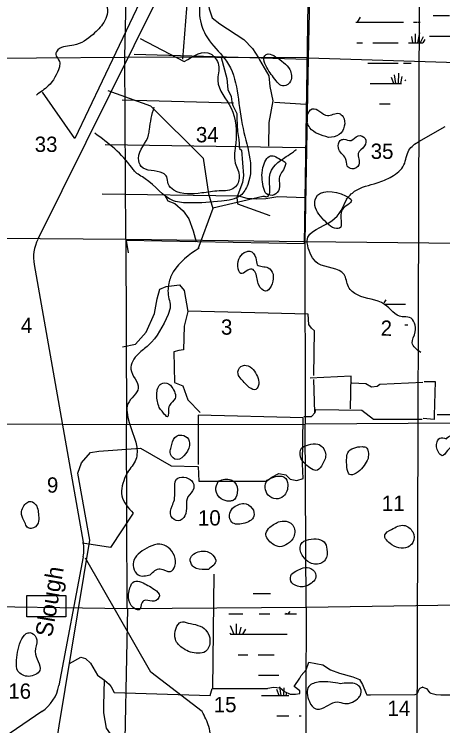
# Model space of a CAD drawing. Extents: x 408847 to 817539, y 923858 to 1151780.
# Drawn here: x 522466 to 535062, y 1031794 to 1052714 of the extents above; entities that cross this region are included whole.
import ezdxf

# ---------------------------------------------------------------- set-up
doc = ezdxf.new("R2010")
doc.units = 0
for name, color, linetype in [('Lakes and Ponds', 7, 'Continuous'), ('Level 42', 7, 'Continuous'), ('Level 43', 7, 'Continuous'), ('Local Roads Paved', 7, 'Continuous'), ('Narrow River Creek and Branch and Slough', 7, 'Continuous'), ('Quad Borders', 7, 'Continuous'), ('Section Lines', 7, 'Continuous'), ('Swamps', 7, 'Continuous'), ('Township  and Range lines', 7, 'Continuous')]:
    doc.layers.add(name, color=color, linetype=linetype)

msp = doc.modelspace()

# ---------------------------------------------------------------- linework, layer by layer
at = {"layer": 'Lakes and Ponds'}
for points in [[(530091, 1050855), (530396, 1050604), (530589, 1050748), (530563, 1051085), (530145, 1051462), (529931, 1051546), (529829, 1051492), (529835, 1051268), (530091, 1050855)], [(531706, 1049094), (532018, 1049174), (532131, 1049702), (532013, 1049795), (531670, 1049737), (531450, 1049859), (531228, 1049934), (531076, 1049716), (531155, 1049375), (531706, 1049094)], [(532249, 1048246), (532387, 1048165), (532599, 1048291), (532576, 1048624), (532758, 1048840), (532780, 1049062), (532574, 1049139), (532372, 1049001), (532150, 1049037), (532050, 1049003), (531993, 1048785), (532203, 1048468), (532249, 1048246)], [(529786, 1047652), (529882, 1047435), (530102, 1047401), (530254, 1047575), (530255, 1047895), (530423, 1048234), (530440, 1048344), (530338, 1048422), (529997, 1048549), (529773, 1048203), (529786, 1047652)], [(531624, 1046610), (531820, 1046447), (532031, 1046425), (532099, 1046952), (532378, 1047238), (532204, 1047376), (531329, 1047311), (531305, 1047091), (531624, 1046610)], [(530073, 1045075), (529929, 1045259), (529611, 1045350), (529565, 1045550), (529387, 1045747), (529285, 1045731), (529041, 1045304), (529130, 1045088), (529453, 1045222), (529557, 1045114), (529658, 1044747), (529850, 1044570), (530079, 1045007), (530073, 1045075)], [(529375, 1041736), (529567, 1041680), (529637, 1041782), (529529, 1042215), (529341, 1042377), (529129, 1042357), (529045, 1042137), (529133, 1041989), (529375, 1041736)], [(526728, 1041150), (526983, 1040883), (527026, 1041212), (527196, 1041418), (527101, 1041749), (526999, 1041847), (526788, 1041851), (526656, 1041531), (526728, 1041150)], [(535168, 1040234), (534976, 1040245), (534894, 1040142), (534933, 1039837), (535042, 1039735), (535200, 1039887), (535723, 1040027), (536268, 1039803), (536476, 1039802), (536610, 1040317), (536361, 1040606), (536036, 1040585), (535712, 1040689), (535724, 1040478), (535631, 1040375), (535314, 1040338), (535168, 1040234)], [(527078, 1039984), (527048, 1039838), (527186, 1039635), (527615, 1040039), (527549, 1040266), (527333, 1040342), (527191, 1040274), (527078, 1039984)], [(531120, 1040053), (530908, 1039951), (530879, 1039705), (531031, 1039482), (531375, 1039310), (531528, 1039482), (531616, 1039802), (531386, 1040077), (531120, 1040053)], [(532869, 1039650), (532799, 1039981), (532691, 1040001), (532273, 1039823), (532236, 1039609), (532356, 1039168), (532572, 1039260), (532869, 1039650)], [(527172, 1038434), (527110, 1038259), (527080, 1037948), (527288, 1037818), (527484, 1037970), (527571, 1038525), (527741, 1038771), (527684, 1038997), (527235, 1039040), (527187, 1038709), (527172, 1038434)], [(529888, 1039011), (529841, 1038794), (529931, 1038576), (530163, 1038464), (530381, 1038541), (530504, 1038886), (530404, 1039102), (530304, 1039133), (529888, 1039011)], [(528471, 1038993), (528392, 1038720), (528550, 1038467), (528790, 1038399), (528898, 1038419), (529022, 1038641), (528939, 1038958), (528835, 1039026), (528471, 1038993)], [(522782, 1037767), (522848, 1037631), (522964, 1037598), (523168, 1037752), (523183, 1037975), (523073, 1038324), (522921, 1038392), (522809, 1038330), (522682, 1038007), (522782, 1037767)], [(528882, 1038195), (528789, 1037986), (528863, 1037780), (529195, 1037739), (529510, 1037953), (529464, 1038184), (529214, 1038330), (528882, 1038195)], [(529980, 1037636), (529866, 1037448), (530063, 1037137), (530277, 1037059), (530502, 1037143), (530682, 1037347), (530653, 1037692), (530519, 1037792), (530278, 1037798), (529980, 1037636)], [(533559, 1037568), (533358, 1037404), (533562, 1037117), (534087, 1037077), (534183, 1037185), (534179, 1037493), (533919, 1037686), (533559, 1037568)], [(531060, 1037252), (530956, 1037204), (530878, 1037086), (530950, 1036778), (531164, 1036585), (531510, 1036581), (531610, 1036673), (531659, 1036983), (531573, 1037198), (531341, 1037290), (531060, 1037252)], [(526466, 1036236), (526109, 1036228), (525967, 1036447), (525985, 1036661), (526434, 1037053), (526745, 1037131), (526989, 1037033), (527188, 1036488), (527056, 1036330), (526752, 1036406), (526466, 1036236)], [(528177, 1036392), (528391, 1036659), (528250, 1036855), (527917, 1036918), (527641, 1036699), (527713, 1036491), (527817, 1036421), (528177, 1036392)], [(530616, 1036256), (530592, 1036045), (530788, 1035900), (531115, 1035930), (531335, 1036212), (531187, 1036419), (530959, 1036433), (530616, 1036256)], [(526211, 1036018), (525993, 1036034), (525866, 1035852), (526034, 1035221), (526136, 1035201), (526222, 1035421), (526330, 1035485), (526582, 1035455), (526735, 1035617), (526589, 1035799), (526211, 1036018)], [(527574, 1034814), (527364, 1034843), (527224, 1034662), (527202, 1034336), (527439, 1034061), (527870, 1033926), (528088, 1033978), (528220, 1034295), (528101, 1034605), (527574, 1034814)], [(522533, 1033720), (522575, 1033402), (522891, 1033247), (523217, 1033421), (523080, 1033976), (523132, 1034321), (522980, 1034521), (522876, 1034527), (522692, 1034351), (522533, 1033720)], [(532054, 1033030), (532272, 1033050), (532620, 1032939), (532658, 1032731), (532596, 1032627), (532179, 1032451), (531965, 1032497), (531439, 1032284), (531332, 1032288), (531141, 1032506), (531123, 1032951), (531442, 1033081), (532054, 1033030)]]:
    msp.add_spline(points, degree=3, dxfattribs=at)
at = {"layer": 'Level 43'}
msp.add_lwpolyline([(522832, 1035627), (523985, 1035627), (523985, 1034998), (522832, 1034998)], close=True, dxfattribs=at)
at = {"layer": 'Local Roads Paved'}
for p, q in [((531084, 1051386), (525993, 1051533)), ((525640, 1050194), (528906, 1050105)), ((531040, 1050064), (530113, 1050123)), ((531010, 1048783), (525140, 1048872)), ((531302, 1041000), (531277, 1041977)), ((528306, 1032893), (528347, 1036249)), ((534305, 1032737), (534371, 1032869)), ((534372, 1032870), (534400, 1032898)), ((534401, 1032899), (534433, 1032919)), ((534434, 1032920), (534470, 1032928)), ((534472, 1032928), (534525, 1032907)), ((534525, 1032907), (534583, 1032887)), ((534584, 1032886), (534617, 1032853)), ((534617, 1032852), (534638, 1032812)), ((532936, 1032703), (534245, 1032711)), ((534247, 1032711), (534303, 1032735)), ((534638, 1032811), (534675, 1032770)), ((534676, 1032769), (534708, 1032749)), ((534710, 1032748), (534788, 1032732)), ((534788, 1032732), (534863, 1032711)), ((534864, 1032711), (535005, 1032707)), ((535005, 1032707), (536736, 1032703))]:
    msp.add_line(p, q, dxfattribs=at)
for points in [[(531002, 1045961), (531145, 1055623), (530184, 1055623), (529836, 1056237), (529754, 1056462)], [(530289, 1055566), (529451, 1055537), (529230, 1055360), (528288, 1054315), (528156, 1054109), (528112, 1053491), (528200, 1052873), (528288, 1052608), (528509, 1052431), (529215, 1051975), (529465, 1051710), (529642, 1051430), (529671, 1051371), (529951, 1050900), (529980, 1050591), (530068, 1050164), (529951, 1049531), (529936, 1048839)], [(528553, 1051445), (528715, 1050827), (528744, 1050503), (528847, 1050297), (528862, 1050135), (528891, 1050032), (529009, 1049796), (529009, 1049649), (529024, 1049266), (529068, 1049031), (529083, 1048766), (529142, 1048722), (529200, 1047971), (529171, 1047768), (529009, 1047326), (529024, 1047135), (529980, 1046796)], [(525052, 1047429), (529053, 1047370), (529303, 1047311), (529598, 1047282), (529863, 1047297), (530216, 1047356), (531022, 1047322)], [(526882, 1047402), (526980, 1047223), (527185, 1047153), (527435, 1046932), (527597, 1046697), (527729, 1046343), (527818, 1046023)], [(531002, 1045961), (525758, 1046064), (525817, 1045696)], [(525644, 1042933), (526032, 1043014), (526339, 1043362), (526584, 1043915), (526666, 1044344), (526748, 1044631), (526932, 1044713), (527321, 1044754), (527464, 1044590), (527566, 1043976), (527464, 1043546), (527443, 1042851), (527300, 1042830), (527157, 1042789), (527177, 1041889), (527423, 1041787), (527566, 1041377), (527934, 1041009)], [(531268, 1042094), (531288, 1043403), (531206, 1043485), (531125, 1043587), (531104, 1043894), (527565, 1043980)], [(534901, 1040942), (535519, 1040942), (535784, 1040942), (538138, 1042120), (538697, 1042355), (539080, 1042443), (539551, 1042443)], [(532352, 1041111), (532372, 1042073), (531166, 1042012)], [(534479, 1041889), (533211, 1041828), (533129, 1041766), (532965, 1041746), (532802, 1041848), (532393, 1041869)], [(534519, 1041913), (534843, 1041913), (534813, 1040913), (534813, 1040795), (534490, 1040824)], [(530981, 1040886), (531206, 1040886), (531309, 1041009), (531329, 1041091), (532679, 1041071), (533027, 1040805), (534458, 1040805)], [(527873, 1039415), (527893, 1038985), (529877, 1038985), (530041, 1039108), (530245, 1039210), (530450, 1039169), (530572, 1039047), (530777, 1039006), (530961, 1039067), (530941, 1039497), (530961, 1040847), (527873, 1040929), (527873, 1039476)], [(524445, 1030071), (523889, 1030540), (523725, 1030826), (523684, 1031154), (523787, 1031788), (524686, 1037251), (524339, 1039216), (524441, 1039523), (524707, 1039830), (524952, 1039871), (526179, 1039952), (527079, 1039441), (527856, 1039420)], [(524088, 1033620), (524421, 1033814), (524564, 1033773), (524707, 1033630), (524911, 1033282), (525116, 1033139), (525259, 1033016), (525320, 1032934), (525402, 1032770), (528225, 1032688), (528286, 1032893), (529906, 1032891)], [(529921, 1032898), (530082, 1032928), (530286, 1032908), (530409, 1032806), (530572, 1032724), (530736, 1032724), (530859, 1032744), (530859, 1032826), (530695, 1032949), (530859, 1033194), (530900, 1033276), (531043, 1033440), (531125, 1033665), (531534, 1033583), (531759, 1033440), (532025, 1033338), (532415, 1033237), (532619, 1033157), (532699, 1033010), (532810, 1032744), (532830, 1032703)], [(525702, 1029946), (525709, 1031297), (525484, 1031297), (525361, 1031461), (525177, 1031727), (525095, 1032177), (525095, 1032402), (525119, 1033136)], [(532830, 1032703), (532866, 1032703), (532936, 1032703)]]:
    msp.add_lwpolyline(points, dxfattribs=at)
for centre, start, end in [((534374, 1032867), 135.0142, 153.4463), ((534403, 1032896), 122.0182, 135.0142), ((534435, 1032916), 102.5348, 122.0182), ((534471, 1032924), 68.953, 102.5348), ((534527, 1032911), 248.953, 250.3372), ((534582, 1032883), 44.9858, 70.3372), ((534614, 1032850), 26.5537, 44.9858), ((532936, 1032707), 270, 270.3651), ((534245, 1032715), 270.3651, 293.2089), ((534301, 1032739), 293.2089, 333.4463), ((534641, 1032813), 206.5537, 221.9731), ((534678, 1032772), 221.9731, 237.9818), ((534710, 1032752), 237.9818, 258.1056), ((534787, 1032728), 74.4686, 78.1056), ((534864, 1032715), 254.4686, 268.3145), ((535005, 1032711), 268.3145, 269.8619)]:
    msp.add_arc(centre, 4, start, end, dxfattribs=at)
at = {"layer": 'Narrow River Creek and Branch and Slough'}
for p, q in [((527458, 1054763), (523159, 1046096)), ((534362, 1048975), (535136, 1049418)), ((523052, 1045353), (524496, 1037194)), ((524494, 1036762), (523780, 1032979)), ((523277, 1032211), (520077, 1030029))]:
    msp.add_line(p, q, dxfattribs=at)
for points in [[(526661, 1054123), (524246, 1049056), (523293, 1050420)], [(527418, 1051391), (527540, 1052879), (527505, 1053543), (527013, 1053760)], [(526169, 1052003), (527465, 1051323)], [(525222, 1050476), (526472, 1050023), (528016, 1048479), (528173, 1047431), (528304, 1047002), (527867, 1045808)], [(528300, 1047020), (529775, 1047369)], [(525963, 1038042), (525293, 1037037), (524475, 1037160)], [(527986, 1032212), (526480, 1033369), (524562, 1036719)]]:
    msp.add_lwpolyline(points, dxfattribs=at)
for centre, start, end in [((524234, 1045562), 153.6172, 190.0394), ((523315, 1036984), 349.3111, 10.0394), ((522601, 1033202), 304.2862, 349.3112)]:
    msp.add_arc(centre, 1200, start, end, dxfattribs=at)
for points in [[(527555, 1055079), (527235, 1055095), (526451, 1055507), (526235, 1055453), (526040, 1055235), (525740, 1055133), (525711, 1054694), (525557, 1054362), (525294, 1054166), (525422, 1053945), (525340, 1053717), (524903, 1053553), (525181, 1052978), (525096, 1052473), (524784, 1052123), (524219, 1051805), (523752, 1051665), (523686, 1051541), (523800, 1051321), (523792, 1051165), (523461, 1050604), (523116, 1050338)], [(527418, 1054504), (527774, 1054373), (527856, 1054271), (527924, 1053135), (527958, 1052432), (528205, 1051931), (528707, 1051333), (529167, 1049469), (529331, 1047708), (529116, 1047386), (528560, 1047222), (527635, 1047165), (527144, 1047230), (526316, 1047879), (525998, 1048101), (525921, 1048205), (524833, 1049218)], [(527465, 1051323), (528238, 1051552), (528471, 1051221), (528449, 1050762), (528840, 1049955), (528975, 1048925), (528964, 1048340), (529082, 1047931), (528941, 1047615), (528489, 1047517), (527978, 1047459), (527156, 1047542), (526992, 1047727), (526948, 1047937), (526838, 1048038), (526196, 1048239), (526120, 1048475), (526417, 1049170), (526437, 1049322), (526578, 1049985)], [(532218, 1047272), (532472, 1047510), (533133, 1047756), (533564, 1047942), (533920, 1048284), (534067, 1048718), (534362, 1048975)], [(529782, 1047368), (529884, 1047349), (529973, 1047920), (530460, 1048528), (530670, 1048670), (530764, 1048740)], [(534420, 1042764), (534164, 1043051), (534253, 1043375), (534081, 1043800), (533867, 1043818), (533349, 1044184), (532553, 1044461), (532293, 1044700), (532161, 1045064), (531393, 1045388), (531091, 1045919), (531073, 1046059), (531801, 1046642), (532247, 1047299)], [(527898, 1045837), (527141, 1045142), (527008, 1044806), (527012, 1044349), (527052, 1044131), (526987, 1043888), (526406, 1042976), (526115, 1042726), (525892, 1042279), (526112, 1041722), (525809, 1041259), (525781, 1041009), (526075, 1039835), (526041, 1039624), (525796, 1039244), (525740, 1039134), (525631, 1038555), (525963, 1038042)], [(524388, 1025190), (524524, 1025460), (524953, 1026048), (525629, 1027250), (526518, 1028657), (526945, 1029065), (527624, 1029601), (527935, 1030062), (528148, 1030671), (528235, 1031254), (528189, 1031768), (527985, 1032214)]]:
    msp.add_spline(points, degree=3, dxfattribs=at)
at = {"layer": 'Quad Borders'}
msp.add_line((534390, 1060351), (534254, 1014913), dxfattribs=at)
at = {"layer": 'Section Lines'}
for p, q in [((525721, 1051447), (525817, 1056814)), ((531243, 1056812), (531103, 1051429)), ((525742, 1046101), (525721, 1051447)), ((531103, 1051429), (525721, 1051447)), ((531103, 1051429), (531007, 1046029)), ((525748, 1046085), (525765, 1040653)), ((531007, 1046029), (531018, 1040664)), ((520503, 1040681), (525765, 1040653)), ((525765, 1040653), (531018, 1040664)), ((525790, 1035239), (525765, 1040653)), ((536367, 1040697), (531018, 1040664)), ((531051, 1035282), (531018, 1040664)), ((531051, 1035282), (536458, 1035369))]:
    msp.add_line(p, q, dxfattribs=at)
for points in [[(520516, 1051416), (525721, 1051447)], [(531103, 1051429), (536425, 1051268)], [(520487, 1035325), (525794, 1035242)], [(525794, 1035242), (525691, 1029949)], [(525794, 1035243), (531051, 1035282)], [(531051, 1035282), (531029, 1029949)]]:
    msp.add_lwpolyline(points, dxfattribs=at)
at = {"layer": 'Swamps'}
for p, q in [((532632, 1052631), (532542, 1052477)), ((533455, 1052477), (533905, 1052477)), ((534246, 1052135), (534246, 1051877)), ((534379, 1052172), (534320, 1051877)), ((533005, 1051877), (533455, 1051877)), ((533455, 1051877), (533755, 1051877)), ((534138, 1052063), (534175, 1051877)), ((532855, 1051277), (533455, 1051277)), ((533455, 1051277), (533755, 1051277)), ((533621, 1050678), (533555, 1050851)), ((533683, 1050677), (533644, 1050930)), ((533762, 1050677), (533767, 1050980)), ((528985, 1034794), (528985, 1034483)), ((529130, 1034697), (529077, 1034483)), ((529263, 1034637), (529173, 1034483)), ((529637, 1033883), (530087, 1033883)), ((530252, 1032684), (530186, 1032857)), ((530315, 1032683), (530275, 1032936))]:
    msp.add_line(p, q, dxfattribs=at)
for points in [[(534779, 1052673), (535256, 1052673)], [(532504, 1052477), (533455, 1052477)], [(534205, 1052477), (534315, 1052477)], [(534336, 1052477), (534399, 1052477)], [(534674, 1052073), (535379, 1052073)], [(532535, 1051877), (532705, 1051877)], [(534055, 1051877), (534476, 1051877)], [(534488, 1052051), (534394, 1051876)], [(534538, 1051975), (534473, 1051878)], [(533905, 1051277), (534132, 1051277)], [(533829, 1050677), (533872, 1050882)], [(532930, 1050677), (533455, 1050677)], [(533455, 1050677), (533847, 1050677)], [(533951, 1050759), (533975, 1050790)], [(533206, 1050077), (533455, 1050077)], [(533455, 1050077), (533512, 1050077)], [(533388, 1044320), (533332, 1044227)], [(533335, 1044187), (533439, 1044187)], [(533439, 1044187), (533969, 1044187)], [(533946, 1043584), (534036, 1043584)], [(529487, 1035683), (529994, 1035683)], [(530522, 1035082), (530576, 1035155)], [(528769, 1035083), (529187, 1035083)], [(529664, 1035083), (529983, 1035083)], [(530423, 1035083), (530766, 1035083)], [(530460, 1035083), (530467, 1035116)], [(528816, 1034745), (528919, 1034483)], [(528806, 1034531), (528827, 1034483)], [(528819, 1034483), (530087, 1034483)], [(530087, 1034483), (530492, 1034483)], [(529045, 1033883), (529337, 1033883)], [(530087, 1033883), (530111, 1033883)], [(529641, 1033283), (530087, 1033283)], [(530087, 1033283), (530243, 1033283)], [(530393, 1032683), (530397, 1032913)], [(529731, 1032683), (530087, 1032683)], [(530087, 1032683), (530533, 1032683)], [(530460, 1032683), (530479, 1032774)], [(530522, 1032682), (530529, 1032691)], [(530187, 1032083), (530537, 1032083)], [(530837, 1032083), (530901, 1032083)]]:
    msp.add_lwpolyline(points, dxfattribs=at)
at = {"layer": 'Township  and Range lines'}
for p, q in [((520519, 1046135), (525742, 1046101)), ((525742, 1046101), (531007, 1046029)), ((531007, 1046029), (536294, 1045972))]:
    msp.add_line(p, q, dxfattribs=at)

# ---------------------------------------------------------------- texts
at = {"layer": 'Level 42'}
msp.add_text('Slough', height=500, rotation=80.239, dxfattribs=at).set_placement((523573, 1034380))
at = {"layer": 'Level 43'}
for s, p in [('34', (527805, 1048948)), ('33', (523067, 1048666)), ('35', (532943, 1048461)), ('4', (522662, 1043342)), ('3', (528542, 1043293)), ('2', (533236, 1043259)), ('9', (523427, 1038648)), ('11', (533271, 1038112)), ('10', (527865, 1037682)), ('16', (522291, 1032589)), ('15', (528329, 1032193)), ('14', (533437, 1032085))]:
    msp.add_text(s, height=450, rotation=359.9063, dxfattribs=at).set_placement(p)

doc.saveas('drawing.dxf')
